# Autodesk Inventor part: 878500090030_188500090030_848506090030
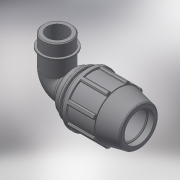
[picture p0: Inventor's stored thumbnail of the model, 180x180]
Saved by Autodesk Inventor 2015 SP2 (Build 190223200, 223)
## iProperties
Created: 2017-02
Part Number: 878500090030_188500090030_848506090030
Material: Generic
Description: PLASSON 90° ELBOW MALE ADAPTOR 90-3"
Document SubType Name: Modeling
Designer: KIM
Mass: 1366.09 g
Surface Area: 1816.46 cm^2
Volume: 1366.09 cm^3
Density: 1 g/cm^3
Appearance: Default
Author: KIM
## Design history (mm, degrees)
derived "87850.ipt"
feature "Solid1::87850.ipt"
tag "TaggingFeature1"
body "Solid1"
other parameters: "d4" = 19.33333, "d5" = 58, "d7" = 152, "d9" = 33.14286, "d11" = 7.73333, "d13" = 120 deg, "d14" = 108, "d15" = 12 deg, "d16" = 132.24, "d18" = 4.5, "d19" = 35 deg, "d20" = 17.5 deg, "d21" = 141.36, "d23" = 0, "d25" = 360 deg, "d27" = 3.04, "d33" = 1.8, "d42" = 85.84, "d43" = 4.56, "d46" = 2.7, "d51" = 232, "d68" = 15.46667, "d73" = 87.884, "d74" = 33, "d75" = 101.0666, "d76" = 61.5188, "d77" = 36.3, "d79" = 35.1536, "d80" = 2.63652, "d83" = 0, "d84" = 0, "d91" = 114, "d93" = 164, "d94" = 87.884, "d95" = 61.5188, "d96" = 15.46667, "d97" = 50 deg, "d98" = 3.86667, "d99" = 128.2728, "d100" = 3.86667, "d101" = 3.86667, "d102" = 10.13333, "d103" = 0, "E_" = 152, "A_" = 232, "l_" = 164, "l_2" = 33, "G_" = 87.884
